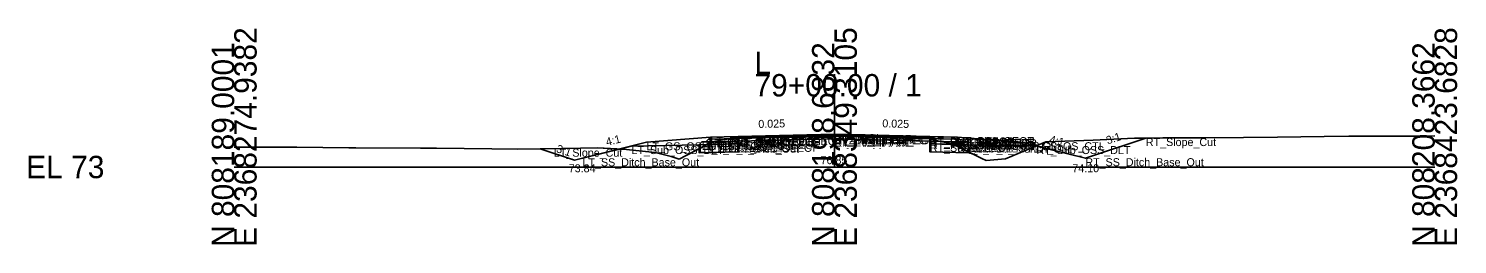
# Model space of a CAD drawing. Extents: x -26 to 8153, y -10 to 9520.
# Drawn here: x 6974.3 to 7152.8, y 9490.3 to 9517.3 of the extents above; entities that cross this region are included whole.
import ezdxf

# ---------------------------------------------------------------- set-up
doc = ezdxf.new("R2010")
doc.units = 0
for name, color, linetype in [('Exist CMT Pavement', 7, 'Continuous'), ('Exist Cross Section Cell', 7, 'Continuous'), ('Exist XS Center Line Elevation Label', 7, 'Continuous'), ('Exist XS Ground Line', 7, 'Continuous'), ('Prop CMT Pvmt Course 1', 7, 'Continuous'), ('Prop CMT Pvmt Course 1 Wedge', 7, 'Continuous'), ('Prop CMT Pvmt Course 2', 7, 'Continuous'), ('Prop CMT Pvmt Course 2 Wedge', 7, 'Continuous'), ('Prop CMT Pvmt Course 3', 7, 'Continuous'), ('Prop CMT Pvmt Course 3 Wedge', 7, 'Continuous'), ('Prop CMT Pvmt Surface', 7, 'Continuous'), ('Prop CMT Pvmt Surface Shoulder', 7, 'Continuous'), ('Prop CMT Pvmt Wedge Surface 1', 7, 'Continuous'), ('Prop CMT Pvmt Wedge Surface 2', 7, 'Continuous'), ('Prop CMT Pvmt Wedge Surface 3', 7, 'Continuous'), ('Prop CMT Shallow Undercut', 7, 'Continuous'), ('Prop CMT Shallow Undercut Boundary', 7, 'Continuous'), ('Prop CMT Shld Paved Course 1', 7, 'Continuous'), ('Prop CMT Shld Paved Course 2', 7, 'Continuous'), ('Prop CMT Shld Paved Course 3', 7, 'Continuous'), ('Prop CMT Slope Grass', 7, 'Continuous'), ('Prop CMT Subgrade Earthwork', 7, 'Continuous'), ('Prop XS Ditch Standard Text', 7, 'Continuous'), ('Prop XS Earthwork Shape', 7, 'Continuous'), ('Prop XS SE Text', 7, 'Continuous'), ('Prop XS Side Slope Text', 7, 'Continuous'), ('Prop XS Subgrade Earthwork', 7, 'Continuous'), ('Scratch_Level_2', 7, 'Continuous'), ('Scratch_Level_6', 7, 'Continuous')]:
    doc.layers.add(name, color=color, linetype=linetype)

msp = doc.modelspace()

# ---------------------------------------------------------------- linework, layer by layer
at = {"layer": 'Exist CMT Pavement'}
for p, q in [((7062.94, 9503.74), (7064.47, 9503.77)), ((7064.47, 9503.77), (7075.01, 9503.85)), ((7075.01, 9503.85), (7085.48, 9503.58)), ((7085.48, 9503.58), (7086.9, 9503.53))]:
    msp.add_line(p, q, dxfattribs=at)
at = {"layer": 'Exist Cross Section Cell'}
for p, q in [((7075, 9500), (7075, 9511.63)), ((7000, 9500), (7075, 9500)), ((7075, 9500), (7150, 9500))]:
    msp.add_line(p, q, dxfattribs=at)
at = {"layer": 'Exist XS Ground Line'}
for p, q in [((7059.68, 9503.14), (7062.05, 9503.56)), ((7062.05, 9503.56), (7062.94, 9503.74)), ((7062.94, 9503.74), (7064.47, 9503.77)), ((7064.47, 9503.77), (7075.01, 9503.85)), ((7075.01, 9503.85), (7085.48, 9503.58)), ((7085.48, 9503.58), (7086.9, 9503.53)), ((7086.9, 9503.53), (7087.56, 9503.36)), ((7087.56, 9503.36), (7088.07, 9503.25)), ((7101.42, 9503.13), (7107.33, 9503.36)), ((7107.33, 9503.36), (7112.49, 9503.61)), ((7112.49, 9503.61), (7116.03, 9503.63)), ((7116.03, 9503.63), (7121.42, 9503.64)), ((7121.42, 9503.64), (7126.12, 9503.7)), ((7126.12, 9503.7), (7130.34, 9503.73)), ((7130.34, 9503.73), (7136.2, 9503.81)), ((7136.2, 9503.81), (7139.26, 9503.84)), ((7139.26, 9503.84), (7146.29, 9503.84)), ((7146.29, 9503.84), (7148.19, 9503.86)), ((7148.19, 9503.86), (7150, 9503.88)), ((7000, 9502.48), (7005.1, 9502.5)), ((7005.1, 9502.5), (7005.41, 9502.5)), ((7005.41, 9502.5), (7007.83, 9502.47)), ((7007.83, 9502.47), (7014.34, 9502.41)), ((7014.34, 9502.41), (7015.19, 9502.4)), ((7015.19, 9502.4), (7023.26, 9502.35)), ((7023.26, 9502.35), (7025.27, 9502.37)), ((7025.27, 9502.37), (7032.18, 9502.28)), ((7032.18, 9502.28), (7035.36, 9502.23)), ((7035.36, 9502.23), (7041.11, 9502.3)), ((7041.11, 9502.3), (7045.44, 9502.39)), ((7045.44, 9502.39), (7048.6, 9502.22)), ((7048.6, 9502.22), (7052.61, 9501.81)), ((7052.61, 9501.81), (7054.61, 9501.32)), ((7056.48, 9501.42), (7059.68, 9503.14)), ((7088.07, 9503.25), (7089.78, 9502.88)), ((7089.78, 9502.88), (7092.02, 9501.77)), ((7092.02, 9501.77), (7093.43, 9501.07)), ((7096.36, 9501.03), (7098.75, 9502.02)), ((7098.75, 9502.02), (7101.42, 9503.13)), ((7054.61, 9501.32), (7055.61, 9501)), ((7055.61, 9501), (7056.48, 9501.42)), ((7093.43, 9501.07), (7093.94, 9500.81)), ((7093.94, 9500.81), (7096.36, 9501.03))]:
    msp.add_line(p, q, dxfattribs=at)
at = {"layer": 'Prop CMT Pvmt Course 1'}
for points in [[(7075, 9504.12), (7059.52, 9503.73)], [(7059.52, 9503.73), (7059.52, 9503.48)], [(7059.52, 9503.48), (7062.94, 9503.57)], [(7062.94, 9503.69), (7075, 9503.99)], [(7062.94, 9503.57), (7062.94, 9503.69)], [(7075, 9503.87), (7075, 9504.12)], [(7075, 9504.12), (7090.35, 9503.74)], [(7075, 9503.87), (7075, 9504.12)], [(7075, 9503.99), (7075, 9503.87), (7075, 9503.87)], [(7086.91, 9503.7), (7075, 9503.99)], [(7075, 9503.99), (7075, 9503.87), (7075, 9503.87)], [(7086.91, 9503.57), (7086.91, 9503.7)], [(7090.35, 9503.49), (7086.91, 9503.57)], [(7090.35, 9503.74), (7090.35, 9503.49)]]:
    msp.add_lwpolyline(points, dxfattribs=at)
at = {"layer": 'Prop CMT Pvmt Course 1 Wedge'}
for points in [[(7075, 9503.99), (7062.94, 9503.69)], [(7075, 9503.99), (7086.91, 9503.7)]]:
    msp.add_lwpolyline(points, dxfattribs=at)
at = {"layer": 'Prop CMT Pvmt Course 2'}
for points in [[(7062.94, 9503.57), (7059.52, 9503.48)], [(7059.52, 9503.48), (7059.52, 9503.15)], [(7062.94, 9503.24), (7062.94, 9503.57)], [(7086.91, 9503.24), (7086.91, 9503.57)], [(7086.91, 9503.57), (7090.35, 9503.49)], [(7090.35, 9503.49), (7090.35, 9503.16)], [(7059.52, 9503.15), (7062.94, 9503.24)], [(7090.35, 9503.16), (7086.91, 9503.24)]]:
    msp.add_lwpolyline(points, dxfattribs=at)
at = {"layer": 'Prop CMT Pvmt Course 2 Wedge'}
for points in [[(7075, 9503.87), (7062.94, 9503.57)], [(7075, 9503.87), (7086.91, 9503.57)]]:
    msp.add_lwpolyline(points, dxfattribs=at)
at = {"layer": 'Prop CMT Pvmt Course 3'}
for points in [[(7062.94, 9503.24), (7059.52, 9503.15)], [(7059.52, 9503.15), (7059.52, 9502.82)], [(7059.52, 9502.82), (7062.94, 9502.9)], [(7062.94, 9502.9), (7062.94, 9503.24)], [(7086.91, 9503.24), (7090.35, 9503.16)], [(7086.91, 9502.91), (7086.91, 9503.24)], [(7090.35, 9502.82), (7086.91, 9502.91)], [(7090.35, 9503.16), (7090.35, 9502.82)]]:
    msp.add_lwpolyline(points, dxfattribs=at)
at = {"layer": 'Prop CMT Pvmt Course 3 Wedge'}
for points in [[(7075, 9503.54), (7062.94, 9503.24)], [(7075, 9503.54), (7086.91, 9503.24)]]:
    msp.add_lwpolyline(points, dxfattribs=at)
at = {"layer": 'Prop CMT Pvmt Surface'}
for points in [[(7075, 9504.12), (7059.52, 9503.73)], [(7075, 9504.12), (7090.35, 9503.74)]]:
    msp.add_lwpolyline(points, dxfattribs=at)
at = {"layer": 'Prop CMT Pvmt Surface Shoulder'}
for points in [[(7059.52, 9503.73), (7059.52, 9503.73)], [(7090.35, 9503.74), (7090.35, 9503.74)]]:
    msp.add_lwpolyline(points, dxfattribs=at)
at = {"layer": 'Prop CMT Pvmt Wedge Surface 1'}
for points in [[(7059.52, 9503.48), (7059.52, 9503.73)], [(7062.94, 9503.57), (7059.52, 9503.48)], [(7075, 9503.99), (7062.94, 9503.69)], [(7062.94, 9503.69), (7062.94, 9503.57)], [(7075, 9503.99), (7086.91, 9503.7)], [(7086.91, 9503.7), (7086.91, 9503.57)], [(7086.91, 9503.57), (7090.35, 9503.49)], [(7090.35, 9503.49), (7090.35, 9503.74)]]:
    msp.add_lwpolyline(points, dxfattribs=at)
at = {"layer": 'Prop CMT Pvmt Wedge Surface 2'}
for points in [[(7075, 9503.87), (7059.52, 9503.48)], [(7059.52, 9503.48), (7059.52, 9503.73)], [(7075, 9503.87), (7090.35, 9503.49)], [(7090.35, 9503.49), (7090.35, 9503.74)]]:
    msp.add_lwpolyline(points, dxfattribs=at)
at = {"layer": 'Prop CMT Pvmt Wedge Surface 3'}
for points in [[(7059.52, 9503.15), (7059.52, 9503.73)], [(7075, 9503.54), (7059.52, 9503.15)], [(7075, 9503.54), (7090.35, 9503.16)], [(7090.35, 9503.16), (7090.35, 9503.74)]]:
    msp.add_lwpolyline(points, dxfattribs=at)
at = {"layer": 'Prop CMT Shallow Undercut'}
for points in [[(7058.09, 9501.79), (7062.94, 9501.9), (7062.94, 9502.9), (7059.07, 9502.81), (7058.09, 9502.29)], [(7086.91, 9502.91), (7089.86, 9502.84), (7091.78, 9501.88), (7091.78, 9501.79), (7086.91, 9501.91)]]:
    msp.add_lwpolyline(points, close=True, dxfattribs=at)
at = {"layer": 'Prop CMT Shallow Undercut Boundary'}
for p, q in [((7058.09, 9502.79), (7058.09, 9501.79)), ((7058.09, 9501.79), (7062.94, 9501.9)), ((7062.94, 9502.9), (7062.94, 9501.9)), ((7086.91, 9502.91), (7086.91, 9501.91)), ((7091.78, 9501.79), (7086.91, 9501.91)), ((7091.78, 9502.79), (7091.78, 9501.79))]:
    msp.add_line(p, q, dxfattribs=at)
at = {"layer": 'Prop CMT Shld Paved Course 1'}
for points in [[(7059.52, 9503.73), (7059.27, 9503.48)], [(7059.27, 9503.48), (7059.52, 9503.48)], [(7059.52, 9503.73), (7059.52, 9503.73)], [(7059.52, 9503.48), (7059.52, 9503.73)], [(7090.35, 9503.74), (7090.35, 9503.74)], [(7090.35, 9503.74), (7090.61, 9503.48)], [(7090.35, 9503.49), (7090.35, 9503.74)], [(7090.61, 9503.48), (7090.35, 9503.49)]]:
    msp.add_lwpolyline(points, dxfattribs=at)
at = {"layer": 'Prop CMT Shld Paved Course 2'}
for points in [[(7059.52, 9503.48), (7059.27, 9503.48), (7058.93, 9503.14)], [(7059.52, 9503.15), (7059.52, 9503.48)], [(7090.35, 9503.49), (7090.61, 9503.48), (7090.94, 9503.14)], [(7090.35, 9503.16), (7090.35, 9503.49)], [(7058.93, 9503.14), (7059.52, 9503.15)], [(7090.94, 9503.14), (7090.35, 9503.16)]]:
    msp.add_lwpolyline(points, dxfattribs=at)
at = {"layer": 'Prop CMT Shld Paved Course 3'}
for points in [[(7059.52, 9503.15), (7058.93, 9503.14), (7058.43, 9503.13), (7058.09, 9502.79)], [(7058.09, 9502.79), (7059.52, 9502.82)], [(7059.52, 9502.82), (7059.52, 9503.15)], [(7090.35, 9503.16), (7090.94, 9503.14), (7091.44, 9503.13), (7091.78, 9502.79)], [(7090.35, 9502.82), (7090.35, 9503.16)], [(7091.78, 9502.79), (7090.35, 9502.82)]]:
    msp.add_lwpolyline(points, dxfattribs=at)
at = {"layer": 'Prop CMT Slope Grass'}
for p, q in [((7059.52, 9503.73), (7051.52, 9503.09)), ((7042.51, 9500.84), (7038.24, 9502.27)), ((7051.52, 9503.09), (7042.51, 9500.84))]:
    msp.add_line(p, q, dxfattribs=at)
msp.add_lwpolyline([(7090.35, 9503.74), (7098.35, 9503.1), (7106.35, 9501.1), (7113.91, 9503.62)], dxfattribs=at)
at = {"layer": 'Prop CMT Subgrade Earthwork'}
for points in [[(7062.94, 9502.9), (7062.94, 9503.74)], [(7086.91, 9502.91), (7086.9, 9503.53)], [(7058.09, 9502.79), (7049.64, 9502.62)], [(7059.52, 9502.82), (7058.09, 9502.79)], [(7062.94, 9502.9), (7059.52, 9502.82)], [(7086.91, 9502.91), (7090.35, 9502.82)], [(7090.35, 9502.82), (7091.78, 9502.79)], [(7091.78, 9502.79), (7100.24, 9502.62)]]:
    msp.add_lwpolyline(points, dxfattribs=at)
at = {"layer": 'Prop XS Earthwork Shape'}
for points in [[(7059.07, 9502.81), (7059.68, 9503.14), (7062.05, 9503.56), (7062.94, 9503.74), (7062.94, 9502.9), (7059.52, 9502.82)], [(7089.78, 9502.88), (7089.87, 9502.83), (7086.91, 9502.91), (7086.9, 9503.53), (7087.56, 9503.36), (7088.07, 9503.25)], [(7100.24, 9502.62), (7106.35, 9501.1), (7113.91, 9503.62), (7112.49, 9503.61), (7107.33, 9503.36), (7101.42, 9503.13), (7100.21, 9502.63)], [(7041.11, 9502.3), (7045.44, 9502.39), (7048.13, 9502.24), (7042.51, 9500.84), (7038.24, 9502.27)], [(7055.61, 9501), (7056.48, 9501.42), (7058.09, 9502.29), (7058.09, 9502.79), (7049.64, 9502.62), (7048.13, 9502.24), (7048.6, 9502.22), (7052.61, 9501.81), (7054.61, 9501.32)], [(7058.09, 9502.29), (7059.07, 9502.81), (7059.52, 9502.82), (7062.94, 9502.9), (7062.94, 9501.9), (7058.09, 9501.79)], [(7058.09, 9502.29), (7059.07, 9502.81), (7058.09, 9502.79)], [(7091.78, 9501.88), (7091.78, 9501.79), (7086.91, 9501.91), (7086.91, 9502.91), (7089.87, 9502.83)], [(7091.78, 9502.79), (7091.78, 9501.88), (7089.87, 9502.83), (7090.35, 9502.82)], [(7091.78, 9501.88), (7092.02, 9501.77), (7093.43, 9501.07), (7093.94, 9500.81), (7096.36, 9501.03), (7098.75, 9502.02), (7100.2, 9502.63), (7091.78, 9502.79)]]:
    msp.add_lwpolyline(points, close=True, dxfattribs=at)
at = {"layer": 'Prop XS Subgrade Earthwork'}
for p, q in [((7058.09, 9502.79), (7062.94, 9502.9)), ((7086.91, 9502.91), (7091.78, 9502.79))]:
    msp.add_line(p, q, dxfattribs=at)
at = {"layer": 'Scratch_Level_6'}
for points in [[(7058.09, 9501.79), (7062.94, 9501.9), (7062.94, 9502.9), (7059.07, 9502.81), (7058.09, 9502.29)], [(7086.91, 9502.91), (7089.86, 9502.84), (7091.78, 9501.88), (7091.78, 9501.79), (7086.91, 9501.91)]]:
    msp.add_lwpolyline(points, close=True, dxfattribs=at)

# ---------------------------------------------------------------- texts
at = {"layer": 'Exist Cross Section Cell'}
for s, p in [('E 2368274.9382', (7002.8, 9490)), ('E 2368349.3105', (7077.8, 9490)), ('E 2368423.6828', (7152.8, 9490)), ('N 808189.0001', (7000, 9490)), ('N 808198.6832', (7075, 9490)), ('N 808208.3662', (7150, 9490))]:
    msp.add_text(s, height=2.8, rotation=90, dxfattribs=at).set_placement(p)
for s, p in [('L', (7065, 9511.63)), ('79+00.00 / 1', (7065, 9508.83)), ('EL 73', (6974, 9498.6))]:
    msp.add_text(s, height=2.8, dxfattribs=at).set_placement(p)
at = {"layer": 'Exist XS Center Line Elevation Label'}
msp.add_text('76.85', height=1, dxfattribs=at).set_placement((7073.27, 9500.35))
at = {"layer": 'Prop XS Ditch Standard Text'}
for s, p in [('73.84', (7041.8, 9499.34)), ('74.10', (7104.72, 9499.35))]:
    msp.add_text(s, height=1, dxfattribs=at).set_placement(p)
at = {"layer": 'Prop XS SE Text'}
for rotation, p in [(1.4321, (7065.5, 9504.88)), (358.5679, (7080.97, 9504.97))]:
    msp.add_text('0.025', height=1, rotation=rotation, dxfattribs=at).set_placement(p)
at = {"layer": 'Prop XS Side Slope Text'}
for s, rotation, p in [('4:1', 14.0362, (7046.57, 9502.63)), ('4:1', 345.9638, (7101.77, 9503.02)), ('3:1', 18.4332, (7109.14, 9502.82)), ('3:1', 341.5668, (7040.16, 9501.88))]:
    msp.add_text(s, height=1, rotation=rotation, dxfattribs=at).set_placement(p)
at = {"layer": 'Scratch_Level_2'}
for s, p in [('LT_PS2_OEOP', (7059.27, 9502.48)), ('LT_PV1_OEOT', (7059.52, 9502.73)), ('LT_PS1_OEOP', (7059.52, 9502.73)), ('LT_PV2_OEOT', (7059.52, 9502.48)), ('LT_Sub Tie Out', (7062.94, 9502.74)), ('LT_PV_OEEOP_EG', (7062.94, 9502.74)), ('LT_PV1_OEEOP', (7062.94, 9502.69)), ('LT_PV2_OEEOP', (7062.94, 9502.57)), ('PV1_PGL', (7075, 9503.12)), ('RT_PV1_IEEOP', (7075, 9502.99)), ('LT_PV1_IEEOP', (7075, 9502.99)), ('RT_PV2_IEEOP', (7075, 9502.87)), ('LT_PV2_IEEOP', (7075, 9502.87)), ('PV2_PGL', (7075, 9502.87)), ('RT_PV_IEEOP_EG', (7075, 9502.85)), ('LT_PV_IEEOP_EG', (7075, 9502.85)), ('RT_PV3_IEEOP', (7075, 9502.54)), ('LT_PV3_IEEOP', (7075, 9502.54)), ('RT_Sub Tie Out', (7086.9, 9502.53)), ('RT_PV_OEEOP_EG', (7086.9, 9502.53)), ('RT_PV1_OEEOP', (7086.91, 9502.7)), ('RT_PV2_OEEOP', (7086.91, 9502.57)), ('RT_PV1_OEOT', (7090.35, 9502.74)), ('RT_PS1_OEOP', (7090.35, 9502.74)), ('RT_PV2_OEOT', (7090.35, 9502.49)), ('RT_PS2_OEOP', (7090.61, 9502.48)), ('RT_Slope_Cut', (7113.91, 9502.62)), ('LT_Slope_Cut', (7039.94, 9501.29)), ('LT_Sub_OSS_DLT', (7049.64, 9501.62)), ('LT_GS_OS_CTL', (7051.52, 9502.09)), ('LT_Sub_Trench_Out', (7058.09, 9501.79)), ('LT_PS3_Shelf_Out', (7058.43, 9502.13)), ('LT_PS3_OEOP', (7058.93, 9502.14)), ('LT_PV3_OEOT', (7059.52, 9502.15)), ('LT_Sub_OEOT', (7059.52, 9501.82)), ('LT_PV3_OEEOP', (7062.94, 9502.24)), ('LT_Sub_OEEOP', (7062.94, 9501.9)), ('RT_PV3_OEEOP', (7086.91, 9502.24)), ('RT_Sub_OEEOP', (7086.91, 9501.91)), ('RT_PV3_OEOT', (7090.35, 9502.16)), ('RT_Sub_OEOT', (7090.35, 9501.82)), ('RT_PS3_OEOP', (7090.94, 9502.14)), ('RT_PS3_Shelf_Out', (7091.44, 9502.13)), ('RT_Sub_Trench_Out', (7091.78, 9501.79)), ('RT_GS_OS_CTL', (7098.35, 9502.1)), ('RT_Sub_OSS_DLT', (7100.24, 9501.62)), ('LT_SS_Ditch_Base_Out', (7043.52, 9500.09)), ('RT_SS_Ditch_Base_Out', (7106.35, 9500.1))]:
    msp.add_text(s, height=1, dxfattribs=at).set_placement(p)

doc.saveas('drawing.dxf')
